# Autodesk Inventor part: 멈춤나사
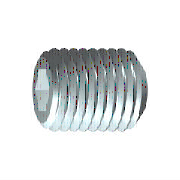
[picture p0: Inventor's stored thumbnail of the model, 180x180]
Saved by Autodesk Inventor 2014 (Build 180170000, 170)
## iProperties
IsCustomPart: 1
Company: 한국ATC센터
Created: 2009-02
Part Number: 멈춤나사
Material: 강, 연강
Description: 6각 소켓 머리 없는 멈춤 나사
Document SubType Name: Modeling
Standard: KS B 1028
Designer: KYOUNG IL JANG
Standards Organization: KS
Language: ko-KR
Size Designation: 납작점M3x6
Categories: <MemberInstance><Categories><Category DisplayName="조임쇠" InternalName="e4da775c-781d-43d5-af7c-5136215cf5a6" Mnemonic="FSTN"><Category DisplayName="볼트" InternalN
Density: 7.86 g/cm^3
Mass: 0.293227 g
Surface Area: 0.779766 cm^2
Volume: 0.0373062 cm^3
Vendor: CBT Solutions
Appearance: 강철
Author: KYOUNG IL JANG
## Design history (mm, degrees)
sketch "스케치1"
  geometry: L1 (0, 0)-(3.5, 0); L2 (6, 0.866)-(6, 1.5); L3 (6, 1.5)-(0, 1.5); L4 (6, 0.866)-(4, 0.866); L5 (4, 0.866)-(3.5, 0); L6 (0, -0.3)-(0, 1.8) reference; L7 (0, 1.5)-(0, 0)
  constraints: 13 end point, 3 parallel, 1 collinear, 1 perpendicular, 1 point on line
  dimensions: "d0" = 2 distance of L2.start L4.end (= INTI); "d1" = 60 deg angle of L5 L1; "d2" = 3 diameter of L3 L1 (= NND); "d3" = 1.73205 diameter of L4 L1 (= 1.1547 x SW); "d5" = 6 distance from line of L2 L3.end (= NLG)
revolve "본체" sketch "스케치1" stored, may be unused: angle "d6" = 90 deg
sketch "스케치2"
  geometry: L1 (-0.433, 0.75)-(0.433, 0.75); L2 (0.433, 0.75)-(0.866, 0); L3 (0.866, 0)-(0.433, -0.75); L4 (0.433, -0.75)-(-0.433, -0.75); L5 (-0.433, -0.75)-(-0.866, 0); L6 (-0.866, 0)-(-0.433, 0.75); A1 r 0.866 centre (0, 0) between (-0.433, 0.75) and (0.433, 0.75) reference; 2 further points
  constraints: 12 end point, 2 point on circle, 1 coincident, 1 horizontal, 11 other
extrude "슬롯" join sketch "스케치2" taper "d9" = 0 deg; stored distance "d21" = 10
workaxis "Work Axis1"
workplane "Work Plane1"
body "Solid1"
chamfer "모따기1" distance "d7" = 0.30673 (= -0.5 x GD1 + 0.5 x NND); stored, may be unused: angle "d8" = 45 deg (= FAWI), second distance "d29" = 0.30673 (= -0.5 x GD1 + 0.5 x NND)
feature "스레드" dims "d11" = 6 (= NLG), "d12" = 0
chamfer "모따기2" distance "d13" = 0.30673 (= -0.5 x GD1 + 0.5 x NND); stored, may be unused: angle "d14" = 45 deg (= FAWI), second distance "d30" = 0.30673 (= -0.5 x GD1 + 0.5 x NND)
other parameters: "NND" = 3 [user parameter; used in 5 equation terms], "NLG" = 6 [user parameter; used in 2 equation terms], "INTI" = 2 [user parameter; used in 1 equation term], "FAWI" = 45 deg [user parameter; used in 2 equation terms], "SW" = 1.5 [user parameter; used in 2 equation terms], "GD1" = 2.38655 (= THREADDIA - 1.2269 x PTC) [user parameter; used in 4 equation terms], "d4" = 0, "FAWI1" = 45 deg [user parameter], "d15" = 0, "d31" = 0, "GUL" = 0.30673 (= 0.61345 x PTC) [user parameter], "SPD" = 2 [user parameter], "TOA" = 30 deg [user parameter], "THREADDIA" = 3 [user parameter; used in 1 equation term], "PTC" = 0.5 [user parameter; used in 4 equation terms], "GAL" = 0.30673 (= 0.61345 x PTC) [user parameter], "E0" = 1.7325 (= 1.155 x SW) [user parameter]
